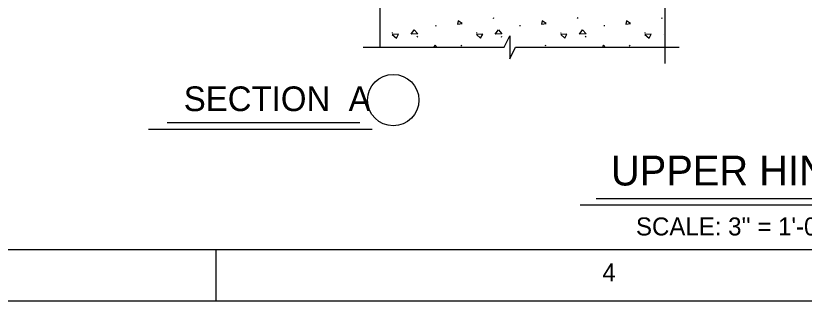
# Model space of a CAD drawing. Extents: x -0.2 to 13.5, y -0.2 to 9.5.
# Drawn here: x 2.351 to 4.91, y 0 to 0.925 of the extents above; entities that cross this region are included whole.
import ezdxf

# ---------------------------------------------------------------- set-up
doc = ezdxf.new("R2010")
doc.units = 0
for name, color, linetype in [('Level 1', 7, 'Continuous'), ('Level 10', 7, 'Continuous'), ('Level 13', 7, 'Continuous'), ('Level 2', 7, 'Continuous'), ('Level 3', 7, 'Continuous')]:
    doc.layers.add(name, color=color, linetype=linetype)

msp = doc.modelspace()

# ---------------------------------------------------------------- linework, layer by layer
at = {"layer": 'Level 1'}
msp.add_line((3.0000000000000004, 0.16666666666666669), (3.0000000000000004, 0), dxfattribs=at)
for points in [[(0, 9.333333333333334), (13.333333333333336, 9.333333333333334), (13.333333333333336, 0), (0, 0)], [(0.5000000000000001, 9.166666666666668), (13.166666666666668, 9.166666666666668), (13.166666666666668, 0.16666666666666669), (0.5000000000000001, 0.16666666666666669)]]:
    msp.add_lwpolyline(points, close=True, dxfattribs=at)
at = {"layer": 'Level 10'}
for p, q in [((3.900770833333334, 0.9164791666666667), (3.902145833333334, 0.9194166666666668)), ((4.174083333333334, 0.9164791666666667), (4.175458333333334, 0.9194166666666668)), ((4.447395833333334, 0.9164791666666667), (4.448770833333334, 0.9194166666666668)), ((3.573458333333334, 0.8684791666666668), (3.5737083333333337, 0.8712291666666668)), ((3.714208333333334, 0.8912916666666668), (3.714770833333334, 0.8949166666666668)), ((3.8467708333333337, 0.8684791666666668), (3.847020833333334, 0.8712291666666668)), ((3.987520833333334, 0.8912916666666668), (3.988083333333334, 0.8949166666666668)), ((4.1200833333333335, 0.8684791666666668), (4.120333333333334, 0.8712291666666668)), ((4.260833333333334, 0.8912916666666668), (4.261395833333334, 0.8949166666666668)), ((4.393395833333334, 0.8684791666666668), (4.393645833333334, 0.8712291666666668)), ((3.653270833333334, 0.8559791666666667), (3.655145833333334, 0.8591041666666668)), ((3.9265833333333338, 0.8559791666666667), (3.928458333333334, 0.8591041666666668)), ((4.199895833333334, 0.8559791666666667), (4.201770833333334, 0.8591041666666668)), ((3.7978333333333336, 0.8267291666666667), (3.796145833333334, 0.8300416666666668)), ((4.0711458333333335, 0.8267291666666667), (4.069458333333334, 0.8300416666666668)), ((4.344458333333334, 0.8267291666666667), (4.342770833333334, 0.8300416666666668))]:
    msp.add_line(p, q, dxfattribs=at)
for points in [[(3.783770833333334, 0.8978541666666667), (3.7989583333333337, 0.8997916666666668), (3.7862083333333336, 0.9083541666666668)], [(4.057083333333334, 0.8978541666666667), (4.0722708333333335, 0.8997916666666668), (4.059520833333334, 0.9083541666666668)], [(4.330395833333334, 0.8978541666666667), (4.345583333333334, 0.8997916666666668), (4.332833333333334, 0.9083541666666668)], [(3.633645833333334, 0.8658541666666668), (3.643708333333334, 0.8791666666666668), (3.655020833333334, 0.8663541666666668)], [(3.9069583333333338, 0.8658541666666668), (3.917020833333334, 0.8791666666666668), (3.9283333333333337, 0.8663541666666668)], [(4.180270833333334, 0.8658541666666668), (4.190333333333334, 0.8791666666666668), (4.201645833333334, 0.8663541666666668)], [(3.572520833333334, 0.8644166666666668), (3.585833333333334, 0.8525416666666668), (3.5929583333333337, 0.8658541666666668)], [(3.8458333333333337, 0.8644166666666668), (3.8591458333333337, 0.8525416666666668), (3.866270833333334, 0.8658541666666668)], [(4.1191458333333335, 0.8644166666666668), (4.132458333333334, 0.8525416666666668), (4.139583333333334, 0.8658541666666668)], [(4.392458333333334, 0.8644166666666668), (4.405770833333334, 0.8525416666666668), (4.412895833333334, 0.8658541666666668)]]:
    msp.add_lwpolyline(points, close=True, dxfattribs=at)
for points in [[(4.453583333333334, 0.8658541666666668), (4.453645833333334, 0.8659479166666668)], [(4.453645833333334, 0.8658645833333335), (4.453583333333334, 0.8658541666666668)], [(3.711770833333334, 0.8297291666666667), (3.706104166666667, 0.8229895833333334)], [(3.7176250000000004, 0.8229895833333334), (3.711770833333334, 0.8297291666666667)], [(4.258395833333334, 0.8297291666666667), (4.2549479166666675, 0.8256458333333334)], [(4.261875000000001, 0.8257187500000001), (4.258395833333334, 0.8297291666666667)]]:
    msp.add_lwpolyline(points, dxfattribs=at)
at = {"layer": 'Level 13'}
msp.add_lwpolyline([(3.935458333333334, 0.8229895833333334), (3.954083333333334, 0.8604895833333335), (3.954083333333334, 0.7855729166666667), (3.972833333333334, 0.8229895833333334)], dxfattribs=at)
at = {"layer": 'Level 2'}
for p, q in [((3.533645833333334, 0.8229895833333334), (3.533645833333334, 2.9982812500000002)), ((4.457645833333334, 0.7700937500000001), (4.457645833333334, 1.4751458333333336)), ((3.4782916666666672, 0.8229895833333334), (3.935458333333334, 0.8229895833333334)), ((3.972833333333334, 0.8229895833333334), (4.503270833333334, 0.8229895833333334))]:
    msp.add_line(p, q, dxfattribs=at)
at = {"layer": 'Level 3'}
for p, q in [((2.8423020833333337, 0.5789479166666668), (3.466979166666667, 0.5789479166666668)), ((2.78184375, 0.5581145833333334), (3.5067395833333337, 0.5581145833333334)), ((4.234572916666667, 0.33271875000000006), (5.219833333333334, 0.33271875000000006)), ((4.182239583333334, 0.3118854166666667), (5.265885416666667, 0.3118854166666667))]:
    msp.add_line(p, q, dxfattribs=at)
msp.add_circle((3.575677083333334, 0.65184375), 0.08333333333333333, dxfattribs=at)

# ---------------------------------------------------------------- texts
at = {"layer": 'Level 1'}
msp.add_text('4', height=0.05841675, dxfattribs=at).set_placement((4.254458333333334, 0.06395833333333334))
at = {"layer": 'Level 3'}
for s, height, p in [('SECTION  A', 0.07999993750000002, (2.8958020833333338, 0.6160937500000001)), ('UPPER HINGE', 0.09666662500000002, (4.282177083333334, 0.37509375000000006)), ("SCALE: 3'' = 1'-0''", 0.05833325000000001, (4.363395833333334, 0.21312500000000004))]:
    msp.add_text(s, height=height, dxfattribs=at).set_placement(p)

doc.saveas('drawing.dxf')
